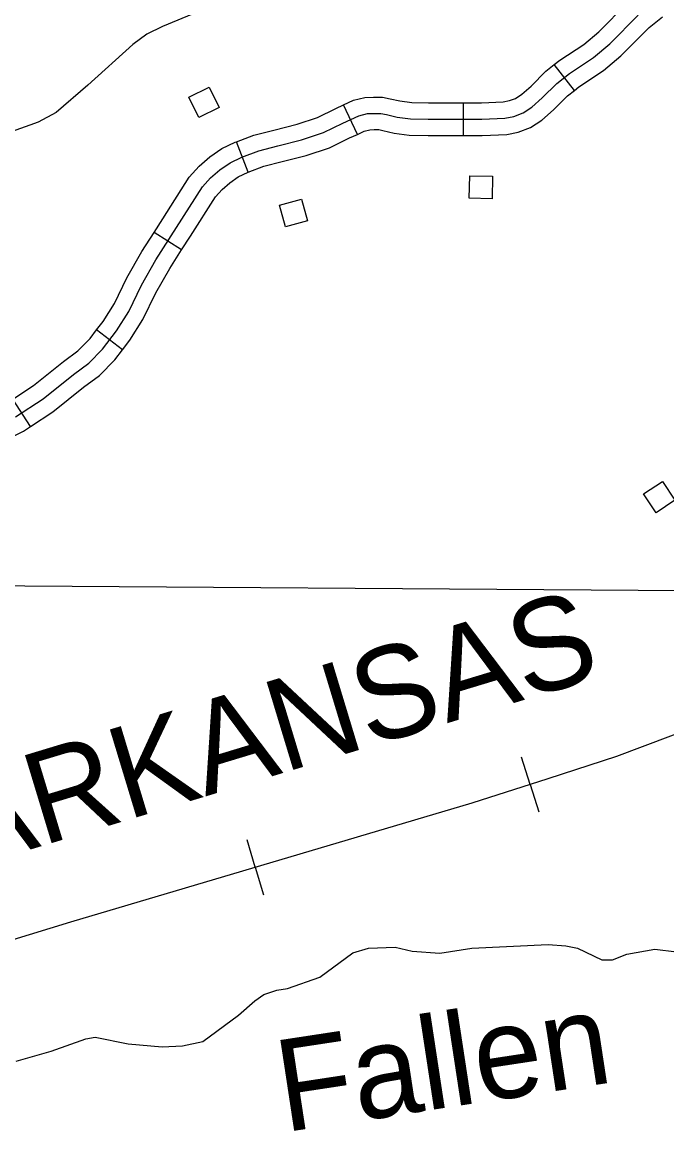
# Model space of a CAD drawing. Extents: x 1370130 to 1380143, y 377636 to 380256.
# Drawn here: x 1377557.8 to 1377640.8, y 379397.1 to 379539.8 of the extents above; entities that cross this region are included whole.
import ezdxf

# ---------------------------------------------------------------- set-up
doc = ezdxf.new("R2010")
doc.units = 0
for name, color, linetype in [('Level 32', 7, 'Continuous'), ('Level 35', 7, 'Continuous'), ('Level 40', 7, 'Continuous'), ('Level 5', 7, 'Continuous'), ('Level 56', 7, 'Continuous')]:
    doc.layers.add(name, color=color, linetype=linetype)

msp = doc.modelspace()

# ---------------------------------------------------------------- linework, layer by layer
at = {"layer": 'Level 32'}
for p, q in [((1377628.87, 379531.07), (1377626.28, 379534.38)), ((1377600.93, 379525.4), (1377599.15, 379529.21)), ((1377614.61, 379525.26), (1377614.61, 379529.46)), ((1377586.85, 379520.53), (1377585.36, 379524.46)), ((1377578.28, 379510.52), (1377574.75, 379512.79)), ((1377570.66, 379497.67), (1377567.34, 379500.24)), ((1377558.84, 379487.8), (1377556.54, 379491.31))]:
    msp.add_line(p, q, dxfattribs=at)
for points in [[(1377626.28, 379534.38), (1377626.99, 379534.94), (1377630.09, 379536.99), (1377632, 379538.61), (1377635.68, 379542.29), (1377637.56, 379543.82)], [(1377556.88, 379489.03), (1377560.45, 379491.36), (1377564.38, 379494.5), (1377566.32, 379495.95), (1377568.08, 379497.76), (1377569.89, 379500.1), (1377571.48, 379502.61), (1377573.11, 379505.97), (1377574.96, 379509.23), (1377577.65, 379513.42), (1377580.96, 379518.63), (1377582.01, 379519.82), (1377583.2, 379520.83), (1377584.53, 379521.76), (1377586.03, 379522.47), (1377588.23, 379523.3), (1377590.7, 379523.92), (1377593.74, 379524.72), (1377596.56, 379525.64), (1377599.03, 379526.83), (1377601.11, 379527.8), (1377602.21, 379528.07), (1377603.05, 379528.11), (1377603.93, 379528.11), (1377604.68, 379527.94), (1377606.04, 379527.63), (1377607.76, 379527.41), (1377610.06, 379527.36), (1377616.93, 379527.36), (1377619.93, 379527.5), (1377621.08, 379527.72), (1377622.27, 379528.16), (1377623.37, 379528.91), (1377624.74, 379530.1), (1377626.59, 379531.95), (1377628.22, 379533.23), (1377631.35, 379535.3), (1377633.42, 379537.07), (1377637.08, 379540.73)], [(1377628.87, 379531.07), (1377629.45, 379531.53), (1377632.62, 379533.62), (1377634.85, 379535.52), (1377638.49, 379539.17), (1377640.2, 379540.55)], [(1377614.61, 379529.46), (1377616.89, 379529.46), (1377619.69, 379529.59), (1377620.51, 379529.75), (1377621.3, 379530.04), (1377622.09, 379530.57), (1377623.3, 379531.63), (1377625.19, 379533.53), (1377626.28, 379534.38)], [(1377599.15, 379529.21), (1377600.41, 379529.8), (1377601.9, 379530.16), (1377602.99, 379530.21), (1377604.17, 379530.21), (1377605.15, 379529.98), (1377606.41, 379529.7), (1377607.92, 379529.51), (1377610.08, 379529.46), (1377614.61, 379529.46)], [(1377614.61, 379525.26), (1377616.98, 379525.26), (1377620.18, 379525.4), (1377621.65, 379525.69), (1377623.24, 379526.28), (1377624.66, 379527.24), (1377626.17, 379528.56), (1377627.99, 379530.38), (1377628.87, 379531.07)], [(1377585.36, 379524.46), (1377587.6, 379525.31), (1377590.18, 379525.96), (1377593.15, 379526.73), (1377595.78, 379527.59), (1377598.13, 379528.73), (1377599.15, 379529.21)], [(1377586.85, 379520.53), (1377588.86, 379521.3), (1377591.22, 379521.89), (1377594.34, 379522.7), (1377597.35, 379523.69), (1377599.93, 379524.94), (1377600.93, 379525.4)], [(1377600.93, 379525.4), (1377601.8, 379525.81), (1377602.51, 379525.98), (1377603.1, 379526.01), (1377603.68, 379526.01), (1377604.2, 379525.89), (1377605.68, 379525.56), (1377607.61, 379525.31), (1377610.04, 379525.26), (1377614.61, 379525.26)], [(1377574.75, 379512.79), (1377575.88, 379514.55), (1377579.27, 379519.9), (1377580.54, 379521.32), (1377581.92, 379522.5), (1377583.47, 379523.58), (1377585.2, 379524.4), (1377585.36, 379524.46)], [(1377578.28, 379510.52), (1377579.42, 379512.29), (1377582.64, 379517.36), (1377583.49, 379518.32), (1377584.49, 379519.17), (1377585.58, 379519.94), (1377586.85, 379520.53), (1377586.85, 379520.53)], [(1377567.34, 379500.24), (1377568.17, 379501.31), (1377569.64, 379503.64), (1377571.25, 379506.95), (1377573.16, 379510.32), (1377574.75, 379512.79)], [(1377570.66, 379497.67), (1377571.61, 379498.89), (1377573.31, 379501.59), (1377574.97, 379504.99), (1377576.76, 379508.15), (1377578.28, 379510.52)], [(1377556.54, 379491.31), (1377559.22, 379493.07), (1377563.09, 379496.16), (1377564.93, 379497.54), (1377566.49, 379499.14), (1377567.34, 379500.24)], [(1377558.84, 379487.8), (1377561.69, 379489.66), (1377565.66, 379492.84), (1377567.71, 379494.37), (1377569.67, 379496.38), (1377570.66, 379497.67)], [(1377544.61, 379482.05), (1377546.83, 379482.71), (1377550.45, 379484.05), (1377554.08, 379485.32), (1377557.92, 379487.2), (1377558.84, 379487.8)]]:
    msp.add_lwpolyline(points, dxfattribs=at)
at = {"layer": 'Level 35'}
for points in [[(1377580.28, 379541.14), (1377575.82, 379539.3), (1377573.79, 379538.3), (1377572.02, 379536.97), (1377566.22, 379531.72), (1377562.15, 379528.24)], [(1377562.15, 379528.24), (1377559.82, 379526.98), (1377549.72, 379523.39), (1377546.22, 379521.11)], [(1377556.96, 379406.1), (1377561.47, 379407.35), (1377565.94, 379408.97), (1377567.17, 379409.18), (1377571.39, 379408.3), (1377575.77, 379407.92), (1377578.42, 379408.05), (1377581.02, 379408.62), (1377585.6, 379412), (1377587.71, 379413.84), (1377588.86, 379414.67), (1377590.57, 379415.21), (1377591.91, 379415.42), (1377596.1, 379416.89), (1377600.32, 379420.01), (1377602.37, 379420.62), (1377605.8, 379420.77), (1377607.98, 379420.26), (1377611.54, 379419.97), (1377615.68, 379420.62), (1377625.5, 379421.11), (1377627.77, 379420.92), (1377629.29, 379420.61), (1377632.39, 379419.15), (1377633.79, 379419.14), (1377635.61, 379419.85), (1377639.22, 379420.49), (1377642, 379420.16)]]:
    msp.add_lwpolyline(points, dxfattribs=at)
at = {"layer": 'Level 40'}
for p, q in [((1377623.17, 379441.7), (1377622.05, 379445.22)), ((1377623.17, 379441.7), (1377624.3, 379438.18)), ((1377587.78, 379431.04), (1377586.73, 379434.58)), ((1377587.78, 379431.04), (1377588.83, 379427.5))]:
    msp.add_line(p, q, dxfattribs=at)
msp.add_lwpolyline([(1377768.15, 379522.69), (1377767.46, 379522.41), (1377760.72, 379519.29), (1377750.31, 379513.46), (1377733.16, 379502.56), (1377699.29, 379481.1), (1377677.72, 379467.62), (1377661.8, 379457.51), (1377654.81, 379453.89), (1377644.89, 379449.3), (1377634.29, 379445.31), (1377625.47, 379442.43), (1377615.67, 379439.31), (1377563.97, 379423.98), (1377515.46, 379409.15)], dxfattribs=at)
msp.add_lwpolyline([(1377768.15, 379522.69), (1377767.46, 379522.41), (1377760.72, 379519.29), (1377750.31, 379513.46), (1377733.16, 379502.56), (1377699.29, 379481.1), (1377677.72, 379467.62), (1377661.8, 379457.51), (1377654.81, 379453.89), (1377644.89, 379449.3), (1377634.29, 379445.31), (1377625.47, 379442.43), (1377615.67, 379439.31), (1377563.97, 379423.98), (1377515.46, 379409.15)], dxfattribs=at)
at = {"layer": 'Level 5'}
msp.add_lwpolyline([(1377545.89, 379467.36), (1377643.17, 379466.67)], dxfattribs=at)
at = {"layer": 'Level 56'}
for points in [[(1377581.83, 379531.48), (1377583.13, 379528.87), (1377580.51, 379527.57), (1377579.22, 379530.18)], [(1377618.34, 379520.01), (1377618.27, 379517.1), (1377615.34, 379517.17), (1377615.42, 379520.08)], [(1377593.71, 379517.07), (1377594.49, 379514.26), (1377591.67, 379513.48), (1377590.9, 379516.29)], [(1377640.2, 379480.73), (1377641.82, 379478.31), (1377639.39, 379476.69), (1377637.77, 379479.11)]]:
    msp.add_lwpolyline(points, close=True, dxfattribs=at)

# ---------------------------------------------------------------- texts
at = {"layer": 'Level 35'}
msp.add_text('Fallen', height=11.827, rotation=8.6541, dxfattribs=at).set_placement((1377591.5, 379396.92))
at = {"layer": 'Level 40'}
msp.add_text('ARKANSAS', height=11.827, rotation=16.8546, dxfattribs=at).set_placement((1377550.21, 379430.72))

doc.saveas('drawing.dxf')
